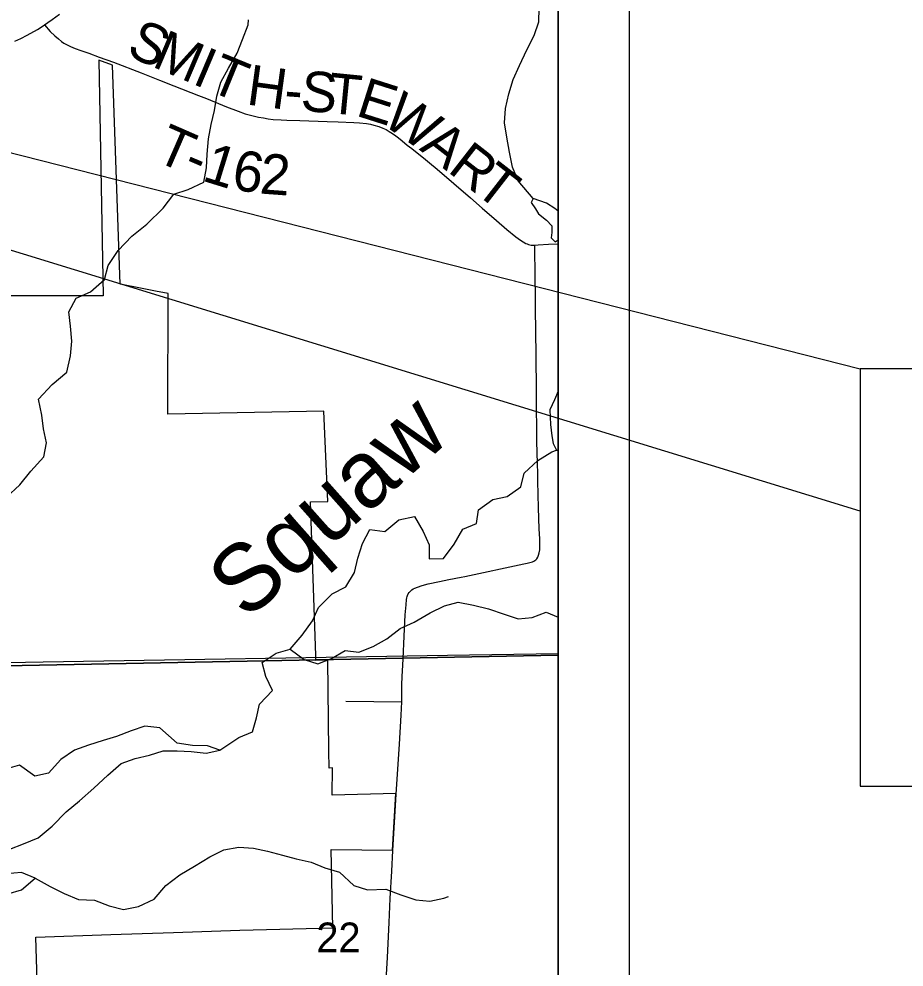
# Model space of a CAD drawing. Extents: x -6.4 to 34, y -4.2 to 22.
# Drawn here: x 8.141 to 9.387, y 15.496 to 16.831 of the extents above; entities that cross this region are included whole.
import ezdxf

# ---------------------------------------------------------------- set-up
doc = ezdxf.new("R2010")
doc.units = 0
for name, color, linetype in [('GM_X_Corporation', 7, 'Continuous'), ('GM_X_County_Road', 7, 'Continuous'), ('GM_X_Major_Lake', 7, 'Continuous'), ('GM_X_Minor_Lake', 7, 'Continuous'), ('GM_X_Minor_River', 7, 'Continuous'), ('GM_X_Minor_River_Text', 7, 'Continuous'), ('GM_X_Section_Text', 7, 'Continuous'), ('GM_X_Township_Road', 7, 'Continuous'), ('GM_X_Township_Road_Text', 7, 'Continuous'), ('SH_Data', 7, 'Continuous'), ('SH_Text', 7, 'Continuous')]:
    doc.layers.add(name, color=color, linetype=linetype)

msp = doc.modelspace()

# ---------------------------------------------------------------- linework, layer by layer
at = {"layer": 'GM_X_Corporation'}
for points in [[(7.0203, 17.4801), (7.0556, 16.0421), (7.0636, 15.9014), (7.2702, 15.904), (7.2926, 15.9044), (8.6815, 15.9311), (8.9, 15.9356), (8.9, 20.7065)], [(8.1709, 15.3391), (8.1644, 15.5386), (8.2703, 15.5422), (8.3586, 15.5451), (8.4519, 15.5482), (8.5827, 15.5514), (8.5805, 15.6617), (8.667, 15.661), (8.6715, 15.7406), (8.5819, 15.7386), (8.5823, 15.7768), (8.5774, 15.7766), (8.5771, 15.8007), (8.5762, 15.8866), (8.5758, 15.9285), (8.5758, 15.9285), (8.559, 15.9281), (8.5587, 15.9349), (8.5514, 16.1514), (8.5759, 16.1519), (8.5702, 16.279), (8.3505, 16.2748), (8.3511, 16.4447), (8.333, 16.4482), (8.3144, 16.4519), (8.2834, 16.458), (8.2725, 16.7665), (8.2533, 16.7735), (8.2594, 16.4413), (8.2531, 16.4413), (8.105, 16.4414)]]:
    msp.add_lwpolyline(points, dxfattribs=at)
for points in [[(7.1124, 14.1), (8.9, 14.1), (8.9, 15.9356), (8.6815, 15.9311), (7.2926, 15.9044), (7.2702, 15.904), (7.0636, 15.9014), (7.0744, 15.3393), (7.0897, 14.8536), (7.0948, 14.7153), (7.0983, 14.5939), (7.1017, 14.4646)], [(8.9, 15.1746), (8.9, 15.9375), (8.744, 15.9349), (8.175, 15.9256), (8.0507, 15.9235), (8.0705, 15.1646)]]:
    msp.add_lwpolyline(points, close=True, dxfattribs=at)
at = {"layer": 'GM_X_County_Road'}
msp.add_lwpolyline([(8.1352, 16.8), (8.1436, 16.8039), (8.1523, 16.8086), (8.1669, 16.8167), (8.1748, 16.8217), (8.1766, 16.8229), (8.1813, 16.8262), (8.1875, 16.8305), (8.1979, 16.8382)], dxfattribs=at)
at = {"layer": 'GM_X_Major_Lake'}
for points in [[(8.1278, 15.6622), (8.1472, 15.6697), (8.1677, 15.6784), (8.1878, 15.695), (8.2073, 15.715), (8.2263, 15.7305), (8.2461, 15.7483), (8.2659, 15.7668), (8.2849, 15.783), (8.3043, 15.7902), (8.3247, 15.7946), (8.3441, 15.801), (8.3638, 15.8009), (8.3835, 15.7997), (8.4046, 15.7977), (8.4238, 15.8017), (8.4062, 15.808), (8.3854, 15.8084), (8.3635, 15.8116), (8.339, 15.8333), (8.3182, 15.8357), (8.2988, 15.8289), (8.2783, 15.8211), (8.2594, 15.8154), (8.2389, 15.8087), (8.2188, 15.8016), (8.1998, 15.7887), (8.1822, 15.7694), (8.1633, 15.765), (8.1418, 15.7806), (8.1221, 15.775)], [(8.1251, 15.5996), (8.1445, 15.6052), (8.1635, 15.6214), (8.1443, 15.6295), (8.1227, 15.6277)]]:
    msp.add_lwpolyline(points, dxfattribs=at)
at = {"layer": 'GM_X_Minor_Lake'}
msp.add_line((8.896, 16.5176), (8.9, 16.5204), dxfattribs=at)
for points in [[(8.9, 16.5609), (8.8952, 16.5643), (8.8835, 16.5719), (8.8646, 16.5785), (8.8619, 16.5728), (8.8683, 16.564), (8.8724, 16.5568), (8.8834, 16.548), (8.8909, 16.54), (8.8912, 16.5309), (8.8904, 16.5233), (8.896, 16.5176)], [(8.9, 16.3073), (8.895, 16.295), (8.8885, 16.281), (8.8891, 16.2604), (8.8909, 16.2445), (8.8931, 16.2335), (8.8976, 16.2243), (8.9, 16.2244)]]:
    msp.add_lwpolyline(points, dxfattribs=at)
at = {"layer": 'GM_X_Minor_River'}
for points in [[(8.8646, 16.5785), (8.8439, 16.6033), (8.8357, 16.6227), (8.8317, 16.644), (8.8277, 16.6649), (8.8244, 16.685), (8.8257, 16.7051), (8.8307, 16.726), (8.8365, 16.7461), (8.8454, 16.7658), (8.8561, 16.7878), (8.8661, 16.8083), (8.8726, 16.8272), (8.8735, 16.8466), (8.874, 16.8675), (8.8798, 16.8891), (8.886, 16.9089), (8.8971, 16.9282), (8.9, 16.9316)], [(8.1226, 16.1575), (8.142, 16.1752), (8.1576, 16.1945), (8.1759, 16.2146), (8.1798, 16.2347), (8.1754, 16.2541), (8.1729, 16.2735), (8.1685, 16.2959), (8.1875, 16.3167), (8.2081, 16.3341), (8.2135, 16.3572), (8.2152, 16.3777), (8.2134, 16.3986), (8.2109, 16.4188), (8.2212, 16.4381), (8.2414, 16.4471), (8.2612, 16.4645), (8.2666, 16.4842), (8.2807, 16.5054), (8.2998, 16.5255), (8.3211, 16.5425), (8.344, 16.5652), (8.3588, 16.5849), (8.3789, 16.5912), (8.401, 16.6014), (8.4049, 16.6219), (8.4058, 16.6409), (8.4078, 16.6625), (8.4113, 16.6826), (8.416, 16.7024), (8.4195, 16.7229), (8.425, 16.7426), (8.4357, 16.7619), (8.4479, 16.7831), (8.4556, 16.8025), (8.4637, 16.8229), (8.4641, 16.8302)], [(8.4238, 15.8017), (8.4502, 15.8195), (8.4696, 15.8274), (8.4754, 15.8475), (8.4793, 15.8665), (8.4976, 15.8858), (8.4882, 15.9056), (8.4831, 15.9254), (8.5032, 15.9382), (8.5225, 15.9442), (8.5397, 15.9638), (8.5542, 15.9839), (8.5627, 16.0029), (8.5817, 16.0221), (8.6011, 16.0319), (8.6133, 16.052), (8.618, 16.0721), (8.6246, 16.0926), (8.6349, 16.1123), (8.6561, 16.1099), (8.6755, 16.1262), (8.6979, 16.1306), (8.7099, 16.1097), (8.7184, 16.0907), (8.7183, 16.0713), (8.7384, 16.0716), (8.7537, 16.092), (8.7659, 16.1129), (8.7849, 16.1208), (8.7877, 16.1401), (8.8082, 16.1548), (8.8283, 16.1589), (8.8473, 16.1725), (8.8523, 16.1919), (8.8714, 16.2096), (8.8911, 16.2218), (8.8976, 16.2243)], [(8.5225, 15.9442), (8.5425, 15.9296), (8.5618, 15.9235), (8.5811, 15.931), (8.6001, 15.9423), (8.6194, 15.9399), (8.6396, 15.9478), (8.6586, 15.9584), (8.6776, 15.9731), (8.6973, 15.9821), (8.7197, 15.9953), (8.7399, 16.0051), (8.7592, 16.01), (8.7808, 16.0061), (8.8019, 16.001), (8.8238, 15.9933), (8.8439, 15.9868), (8.8632, 15.9886), (8.8833, 15.9961), (8.9, 15.9892)], [(8.1635, 15.6214), (8.1846, 15.6099), (8.2047, 15.6), (8.2247, 15.5915), (8.247, 15.5907), (8.2678, 15.5826), (8.2882, 15.5772), (8.309, 15.5817), (8.3311, 15.5918), (8.3478, 15.6111), (8.3672, 15.6262), (8.3878, 15.6383), (8.4094, 15.6515), (8.4295, 15.6613), (8.4504, 15.6653), (8.4712, 15.6637), (8.4909, 15.6595), (8.5117, 15.6541), (8.5313, 15.649), (8.5521, 15.644), (8.5714, 15.6363), (8.5922, 15.6302), (8.6121, 15.6111), (8.6318, 15.6053), (8.6575, 15.6059), (8.6787, 15.5979), (8.6998, 15.5909), (8.7195, 15.589), (8.7392, 15.5934), (8.7457, 15.5957)]]:
    msp.add_lwpolyline(points, dxfattribs=at)
at = {"layer": 'GM_X_Township_Road'}
for p, q in [((8.6012, 15.8708), (8.6798, 15.8699)), ((8.6672, 15.6605), (8.6717, 15.74))]:
    msp.add_line(p, q, dxfattribs=at)
for points in [[(8.1766, 16.8229), (8.185, 16.8139), (8.1913, 16.8078), (8.1964, 16.8032), (8.2008, 16.7997), (8.2042, 16.7974), (8.2077, 16.7952), (8.2132, 16.7926), (8.2201, 16.79), (8.228, 16.7869), (8.2392, 16.783), (8.2539, 16.7778)], [(8.2539, 16.7778), (8.2738, 16.7706), (8.3131, 16.7554), (8.3385, 16.7452), (8.3587, 16.7372), (8.3935, 16.7238), (8.405, 16.7192), (8.4332, 16.7077), (8.4495, 16.7014), (8.4595, 16.6979), (8.4685, 16.6954), (8.4783, 16.6932), (8.4852, 16.692), (8.4918, 16.6908), (8.4986, 16.69), (8.5098, 16.6892), (8.5182, 16.689), (8.5365, 16.6884), (8.575, 16.6871), (8.5905, 16.6865), (8.6123, 16.6856), (8.6203, 16.685), (8.6301, 16.684), (8.6356, 16.6831), (8.6404, 16.682), (8.6475, 16.68), (8.6533, 16.6778), (8.6577, 16.6758), (8.6623, 16.673), (8.6666, 16.67), (8.6714, 16.6666), (8.675, 16.6638), (8.6803, 16.6598), (8.6875, 16.6539), (8.6938, 16.6488), (8.7134, 16.6336), (8.7191, 16.6288), (8.7296, 16.62), (8.7766, 16.5793), (8.7932, 16.5652), (8.8133, 16.5476), (8.8279, 16.535), (8.8404, 16.5247), (8.8469, 16.5198), (8.8506, 16.5174), (8.8546, 16.5154), (8.8565, 16.5146), (8.8581, 16.514), (8.86, 16.5134), (8.8618, 16.5131), (8.8643, 16.5128), (8.867, 16.5128)], [(8.867, 16.5128), (8.8721, 16.5132), (8.8865, 16.5141), (8.9, 16.5149)], [(8.6817, 15.9305), (8.683, 15.9625), (8.6845, 15.9923), (8.6858, 16.0066), (8.6867, 16.014), (8.687, 16.0165), (8.6874, 16.0183), (8.6877, 16.0195), (8.6888, 16.0219), (8.6903, 16.024), (8.6921, 16.0259), (8.6942, 16.0276), (8.6961, 16.0289), (8.698, 16.0298), (8.7021, 16.0315), (8.7086, 16.0337), (8.717, 16.0359), (8.7328, 16.0394), (8.7462, 16.0421), (8.7633, 16.0454), (8.7688, 16.0465), (8.8519, 16.0643), (8.8564, 16.0652), (8.8602, 16.066), (8.8637, 16.0669), (8.8658, 16.0678), (8.8674, 16.0687), (8.8687, 16.0697), (8.8701, 16.0714), (8.8713, 16.0734), (8.8725, 16.0762), (8.8735, 16.0797), (8.8741, 16.0839), (8.8743, 16.0866), (8.8743, 16.09), (8.8743, 16.0932), (8.8742, 16.0992), (8.8735, 16.1134), (8.8722, 16.1432), (8.8716, 16.1804), (8.8712, 16.1915), (8.8708, 16.2052), (8.8704, 16.2207), (8.8701, 16.2363), (8.8699, 16.2549), (8.8695, 16.2838), (8.8693, 16.3076), (8.8689, 16.3581), (8.8683, 16.4243), (8.8682, 16.438), (8.8678, 16.471), (8.8671, 16.5077), (8.867, 16.5128)], [(8.6717, 15.74), (8.6764, 15.81), (8.6789, 15.851), (8.6798, 15.8699), (8.68, 15.8931), (8.6804, 15.9061), (8.6807, 15.9129), (8.6817, 15.9305)], [(8.6574, 15.4699), (8.6595, 15.5097), (8.6621, 15.5593), (8.6637, 15.5928), (8.6659, 15.6313), (8.6672, 15.6605)]]:
    msp.add_lwpolyline(points, dxfattribs=at)
at = {"layer": 'SH_Data'}
for p, q in [((9, 21), (9, 14)), ((8.9, 20.9), (8.9, 14.1))]:
    msp.add_line(p, q, dxfattribs=at)
at = {"layer": 'SH_Text'}
for points in [[(9.3252, 16.3385), (9.3252, 16.1385), (5.5217, 17.3069)], [(12.8366, 16.3385), (9.3252, 16.3385), (9.3252, 15.7511), (12.8366, 15.7511)]]:
    msp.add_lwpolyline(points, close=True, dxfattribs=at)

# ---------------------------------------------------------------- texts
at = {"layer": 'GM_X_Minor_River_Text'}
msp.add_text('Squaw', height=0.09475, rotation=41.6234, dxfattribs=at).set_placement((8.4611, 15.983))
at = {"layer": 'GM_X_Section_Text'}
msp.add_text('22', height=0.04186, rotation=0, dxfattribs=at).set_placement((8.5596, 15.5172))
at = {"layer": 'GM_X_Township_Road_Text'}
for s, rotation, p in [('S', 335.3903, (8.2901, 16.7816)), ('M', 336.9332, (8.3265, 16.765)), ('I', 336.9797, (8.3832, 16.7408)), ('T', 337.75, (8.4055, 16.7313)), ('H', 352.2398, (8.4599, 16.7112)), ('S', 355.6195, (8.5364, 16.7023)), ('T', 354.3077, (8.5743, 16.6994)), ('E', 342.3484, (8.6135, 16.6958)), ('-', 355.6363, (8.5131, 16.7041)), ('W', 325.1673, (8.65, 16.6849)), ('T', 336.4244, (8.3301, 16.6328)), ('A', 322.1443, (8.7034, 16.6478)), ('1', 342.8417, (8.397, 16.6042)), ('R', 322.1418, (8.7429, 16.6171)), ('-', 337.0337, (8.3696, 16.6155)), ('6', 350.7077, (8.4387, 16.592)), ('2', 355.7912, (8.4787, 16.5857)), ('T', 322.142, (8.7797, 16.5884))]:
    msp.add_text(s, height=0.0568, rotation=rotation, dxfattribs=at).set_placement(p)

doc.saveas('drawing.dxf')
